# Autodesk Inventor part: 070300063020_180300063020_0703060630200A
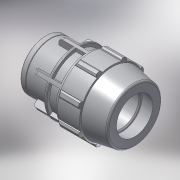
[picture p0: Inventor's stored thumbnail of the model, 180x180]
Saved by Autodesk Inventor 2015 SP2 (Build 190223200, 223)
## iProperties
Created: 2017-02
Part Number: 070300063020_180300063020_0703060630200A
Material: PVC-Piping
Description: PLASSON FEMALE ADAPTOR 63-2"
Document SubType Name: Modeling
Designer: KIM
Mass: 92.6774 g
Surface Area: 199.44 cm^2
Volume: 66.1981 cm^3
Density: 1.4 g/cm^3
Appearance: Smooth - White
Author: KIM
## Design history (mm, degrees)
derived "07030.ipt"
feature "Solid1::07030.ipt"
tag "TaggingFeature1"
body "Solid1"
other parameters: "d2" = 63, "d4" = 21.14286, "d5" = 37, "d7" = 113, "d9" = 21.14286, "d11" = 4.22857, "d12" = 90.4, "d13" = 120 deg, "d14" = 88.2, "d15" = 10 deg, "d16" = 101.7, "d18" = 3.15, "d19" = 35 deg, "d20" = 17.5 deg, "d21" = 105.09, "d23" = 0, "d25" = 360 deg, "d27" = 2.26, "d34" = 5.65, "d35" = 44.4, "d36" = 0, "d42" = 37, "d43" = 3.39, "d46" = 1.89, "d51" = 148, "d53" = 1.26, "d55" = 360 deg, "d62" = 50.4, "d63" = 56.656, "d64" = 49.33333, "d65" = 5.65, "d66" = 0.5, "d67" = 1, "d68" = 9, "d69" = 81.36, "d70" = 2.825, "d_" = 63, "E_" = 113, "H_" = 148, "Rp_" = 56.656
